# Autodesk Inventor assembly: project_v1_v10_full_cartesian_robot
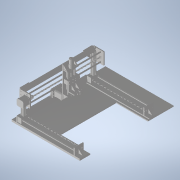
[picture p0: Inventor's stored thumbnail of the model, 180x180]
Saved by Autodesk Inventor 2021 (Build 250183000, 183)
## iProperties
Created: 2026-10
Part Number: project_v1_v10_full_cartesian_robot
Description: STEP AP203
Document SubType Name: Assembly
Designer: hp
Sending System: Autodesk Translation Framework v15.15.0.0
Preprocessor: ST-DEVELOPER v20.2
Title: project_v1_v10_full_cartesian_robot.step
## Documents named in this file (19)
- C:\Users\hp\Documents\Inventor\DOM1_CartesianRobot\project_v1_v10_full_cartesian_robot.iam
- C:\Users\hp\Documents\Inventor\DOM1_CartesianRobot\back_plate.ipt
- C:\Users\hp\Documents\Inventor\DOM1_CartesianRobot\rip.ipt
- C:\Users\hp\Documents\Inventor\DOM1_CartesianRobot\end_support.ipt
- C:\Users\hp\Documents\Inventor\DOM1_CartesianRobot\8mm_Bar.ipt
- C:\Users\hp\Documents\Inventor\DOM1_CartesianRobot\block_Nut_assembly.iam
- C:\Users\hp\Documents\Inventor\DOM1_CartesianRobot\block_Nut_assembly_1.iam
- C:\Users\hp\Documents\Inventor\DOM1_CartesianRobot\Lead Screw T8X8X500.ipt
- C:\Users\hp\Documents\Inventor\DOM1_CartesianRobot\688_bearing.ipt
- C:\Users\hp\Documents\Inventor\DOM1_CartesianRobot\left_right_Legs.ipt
- C:\Users\hp\Documents\Inventor\DOM1_CartesianRobot\Small_Z_Beadge_Assembly.iam
- C:\Users\hp\Documents\Inventor\DOM1_CartesianRobot\GT2 Timing Pulley 20 Tooth_8mm.ipt
- C:\Users\hp\Documents\Inventor\DOM1_CartesianRobot\Low Profile Screw M5_M5 x 25.ipt
- C:\Users\hp\Documents\Inventor\DOM1_CartesianRobot\Nylon Insert Lock Nut M5.ipt
- C:\Users\hp\Documents\Inventor\DOM1_CartesianRobot\GT2 Timing idelar 20 Tooth.ipt
- C:\Users\hp\Documents\Inventor\DOM1_CartesianRobot\Gt2_930.ipt
- C:\Users\hp\Documents\Inventor\DOM1_CartesianRobot\nema17_Assembly.iam
- C:\Users\hp\Documents\Inventor\DOM1_CartesianRobot\Double Tee Nut.ipt
- C:\Users\hp\Documents\Inventor\DOM1_CartesianRobot\project_Base.ipt
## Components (34 placed, 17 different names)
1. back_plate:1
2. rip:7
3. end_support:2
4. rip:8
5. 8mm_Bar:1
6. 8mm_Bar:2
7. block_Nut_assembly:1 [sub-assembly]
8. block_Nut_assembly:2 [sub-assembly]
9. Lead Screw T8X8X500:1
10. Lead Screw T8X8X500:2
11. 688_bearing:5
12. left_right_Legs:1
13. left_right_Legs:2
14. Small_Z_Beadge_Assembly:1 [sub-assembly]
15. GT2 Timing Pulley 20 Tooth_8mm:1
16. GT2 Timing Pulley 20 Tooth_8mm:2
17. Low Profile Screw M5_M5 x 25:1
18. Low Profile Screw M5_M5 x 25:2
19. Nylon Insert Lock Nut M5:1
20. Nylon Insert Lock Nut M5:2
21. GT2 Timing idelar 20 Tooth:1
22. GT2 Timing idelar 20 Tooth:2
23. Nylon Insert Lock Nut M5:3
24. Nylon Insert Lock Nut M5:4
25. Gt2_930:1
26. nema17_Assembly:1 [sub-assembly]
27. Double Tee Nut:1
28. Double Tee Nut:2
29. project_Base:1
30. 688_bearing:7
31. 688_bearing:8
32. rip:11
33. rip:12
34. end_support:3
